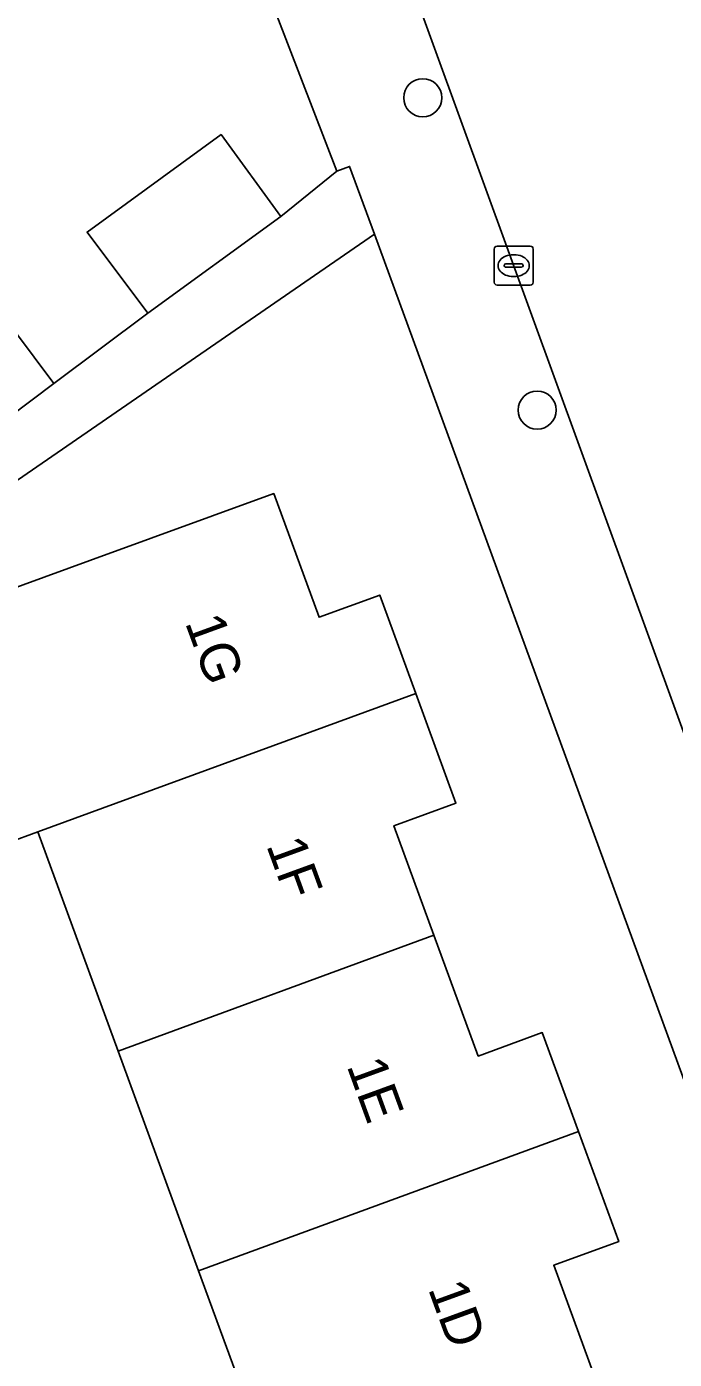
# Model space of a CAD drawing. Extents: x 159217 to 160349, y 381246 to 382172.
# Drawn here: x 159660.85 to 159677.46, y 381381.16 to 381415.33 of the extents above; entities that cross this region are included whole.
import ezdxf

# ---------------------------------------------------------------- set-up
doc = ezdxf.new("R2010")
doc.units = 0
for name, color, linetype in [('IMGEO_Boom', 7, 'Continuous'), ('IMGEO_Erf', 7, 'Continuous'), ('IMGEO_Kolk', 7, 'Continuous'), ('IMGEO_Muur', 7, 'Continuous'), ('IMGEO_Pand', 7, 'Continuous'), ('IMGEO_Pand_nummerreeks', 7, 'Continuous'), ('IMGEO_Rijbaan_lokaal_gesloten', 7, 'Continuous'), ('IMGEO_Voetpad_open', 7, 'Continuous')]:
    doc.layers.add(name, color=color, linetype=linetype)

msp = doc.modelspace()

# ---------------------------------------------------------------- linework, layer by layer
at = {"layer": 'IMGEO_Boom'}
for centre in [(159671.009, 381413.505), (159673.941, 381405.497)]:
    msp.add_circle(centre, 0.489, dxfattribs=at)
at = {"layer": 'IMGEO_Erf'}
for points in [[(159658.991, 381409.59), (159661.552, 381406.18), (159663.964, 381407.98), (159662.403, 381410.06), (159665.837, 381412.563), (159667.368, 381410.462), (159668.803, 381411.624), (159665.367, 381420.544), (159662.997, 381420.056), (159658.298, 381418.348)], [(159669.768, 381410.008), (159656.162, 381400.633), (159656.619, 381399.483), (159647.926, 381396.235), (159648.337, 381395.135), (159650.692, 381395.997), (159652.32, 381391.547), (159653.912, 381387.197), (159651.557, 381386.335), (159652.552, 381383.853), (159654.907, 381384.715), (159656.535, 381380.265), (159658.127, 381375.915), (159655.772, 381375.053), (159656.769, 381372.569), (159659.124, 381373.431), (159660.73, 381369.042), (159662.344, 381364.631), (159659.989, 381363.769), (159661.303, 381359.697), (159681.512, 381366.219)], [(159684.043, 381371.002), (159669.768, 381410.008)], [(159659.05, 381400.391), (159662.471, 381401.643), (159667.19, 381403.357), (159668.351, 381400.186), (159669.904, 381400.754), (159670.828, 381398.23), (159671.856, 381395.422), (159670.267, 381394.841), (159671.296, 381392.029), (159672.429, 381388.933), (159674.072, 381389.534), (159675, 381386.997), (159676.032, 381384.177), (159674.366, 381383.567), (159675.391, 381380.766)], [(159667.315, 381377.807), (159665.258, 381383.427), (159663.196, 381389.062), (159661.14, 381394.681), (159658.904, 381393.862)]]:
    msp.add_lwpolyline(points, dxfattribs=at)
at = {"layer": 'IMGEO_Kolk'}
for p, q in [((159672.838, 381408.776), (159672.838, 381409.628)), ((159672.913, 381409.702), (159673.765, 381409.702)), ((159673.839, 381409.628), (159673.839, 381408.776)), ((159673.097, 381409.196), (159673.097, 381409.208)), ((159673.14, 381409.245), (159673.538, 381409.245)), ((159673.326, 381409.482), (159673.351, 381409.482)), ((159673.581, 381409.208), (159673.581, 381409.196)), ((159673.535, 381409.159), (159673.137, 381409.159)), ((159673.349, 381408.922), (159673.324, 381408.922)), ((159673.765, 381408.702), (159672.913, 381408.702))]:
    msp.add_line(p, q, dxfattribs=at)
for points in [[(159672.838, 381408.776), (159672.838, 381409.628)], [(159672.913, 381409.702), (159673.765, 381409.702)], [(159673.839, 381409.628), (159673.839, 381408.776)], [(159673.765, 381408.702), (159672.913, 381408.702)]]:
    msp.add_lwpolyline(points, dxfattribs=at)
for centre, radius, start, end in [((159672.915, 381409.626), 0.0765, 91.552, 178.448), ((159672.915, 381409.626), 0.0765, 91.552, 178.448), ((159673.763, 381409.626), 0.0765, 1.552, 88.448), ((159673.763, 381409.626), 0.0765, 1.552, 88.448), ((159673.137, 381409.205), 0.0403, 85.8775, 175.7526), ((159673.542, 381409.207), 0.0386, 1.7309, 96.639), ((159673.134, 381409.195), 0.0366, 178.938, 274.7102), ((159673.538, 381409.202), 0.043, 264.8664, 352.4533), ((159672.915, 381408.778), 0.0765, 181.552, 268.448), ((159672.915, 381408.778), 0.0765, 181.552, 268.448), ((159673.763, 381408.778), 0.0765, 271.552, 358.448), ((159673.763, 381408.778), 0.0765, 271.552, 358.448)]:
    msp.add_arc(centre, radius, start, end, dxfattribs=at)
for centre, major_axis, ratio, start_param, end_param in [((159673.325, 381409.202), (-0.387, 0.002), 0.722429, 4.712389, 7.853982), ((159673.35, 381409.202), (-0.39, 0.002), 0.717154, 1.570796, 4.712389)]:
    msp.add_ellipse(centre, major_axis=major_axis, ratio=ratio, start_param=start_param, end_param=end_param, dxfattribs=at)
at = {"layer": 'IMGEO_Muur'}
msp.add_lwpolyline([(159662.997, 381420.056), (159665.367, 381420.544), (159668.803, 381411.624)], dxfattribs=at)
at = {"layer": 'IMGEO_Pand'}
for points in [[(159663.964, 381407.98), (159667.368, 381410.462), (159665.837, 381412.563), (159662.403, 381410.06)], [(159659.215, 381404.424), (159661.552, 381406.18), (159658.991, 381409.59), (159656.644, 381407.827)], [(159667.19, 381403.357), (159662.471, 381401.643), (159659.05, 381400.391), (159656.814, 381399.573), (159658.904, 381393.862), (159661.14, 381394.681), (159670.828, 381398.23), (159669.904, 381400.754), (159668.351, 381400.186)], [(159671.296, 381392.029), (159670.267, 381394.841), (159671.856, 381395.422), (159670.828, 381398.23), (159661.14, 381394.681), (159663.196, 381389.062)], [(159671.296, 381392.029), (159663.196, 381389.062), (159665.258, 381383.427), (159675, 381386.997), (159674.072, 381389.534), (159672.429, 381388.933)], [(159675, 381386.997), (159665.258, 381383.427), (159667.315, 381377.807), (159675.391, 381380.766), (159674.366, 381383.567), (159676.032, 381384.177)]]:
    msp.add_lwpolyline(points, close=True, dxfattribs=at)
at = {"layer": 'IMGEO_Rijbaan_lokaal_gesloten'}
msp.add_lwpolyline([(159665.827, 381426.677), (159667.691, 381423.146), (159668.605, 381421.179), (159670.734, 381416.363), (159679.336, 381392.732), (159686.653, 381372.549), (159694.178, 381375.285), (159691.748, 381381.909), (159685.524, 381398.898), (159678.56, 381418.212), (159677.937, 381419.721), (159675.233, 381425.821), (159673.95, 381428.491), (159671.548, 381432.756), (159663.908, 381429.84), (159663.972, 381429.758), (159664.034, 381429.674)], dxfattribs=at)
at = {"layer": 'IMGEO_Voetpad_open'}
for points in [[(159664.034, 381429.674), (159663.972, 381429.758), (159663.908, 381429.84), (159663.482, 381430.34), (159663.013, 381430.8), (159662.505, 381431.216), (159662.429, 381431.272), (159661.945, 381431.597), (159661.433, 381431.877), (159660.995, 381432.073), (159660.551, 381432.248), (159660.094, 381432.382), (159659.626, 381432.475), (159659.152, 381432.525), (159658.676, 381432.534), (159659.964, 381428.438), (159660.305, 381427.46), (159662.997, 381420.056), (159665.367, 381420.544), (159668.803, 381411.624), (159669.133, 381411.744), (159669.768, 381410.008), (159684.043, 381371.002)], [(159687.289, 381370.542), (159686.653, 381372.549), (159679.336, 381392.732), (159670.734, 381416.363), (159668.605, 381421.179), (159667.691, 381423.146), (159665.827, 381426.677)], [(159656.162, 381400.633), (159669.768, 381410.008), (159669.133, 381411.744), (159668.803, 381411.624), (159667.368, 381410.462), (159663.964, 381407.98), (159661.552, 381406.18), (159659.215, 381404.424)]]:
    msp.add_lwpolyline(points, dxfattribs=at)

# ---------------------------------------------------------------- texts
at = {"layer": 'IMGEO_Pand_nummerreeks'}
for s, rotation, p in [('1G', 290.0419, (159664.906, 381400.052)), ('1F', 290.0441, (159666.988, 381394.34)), ('1E', 290.0441, (159669.05, 381388.686)), ('1D', 290.0441, (159671.136, 381382.97))]:
    msp.add_text(s, height=1, rotation=rotation, dxfattribs=at).set_placement(p)

doc.saveas('drawing.dxf')
